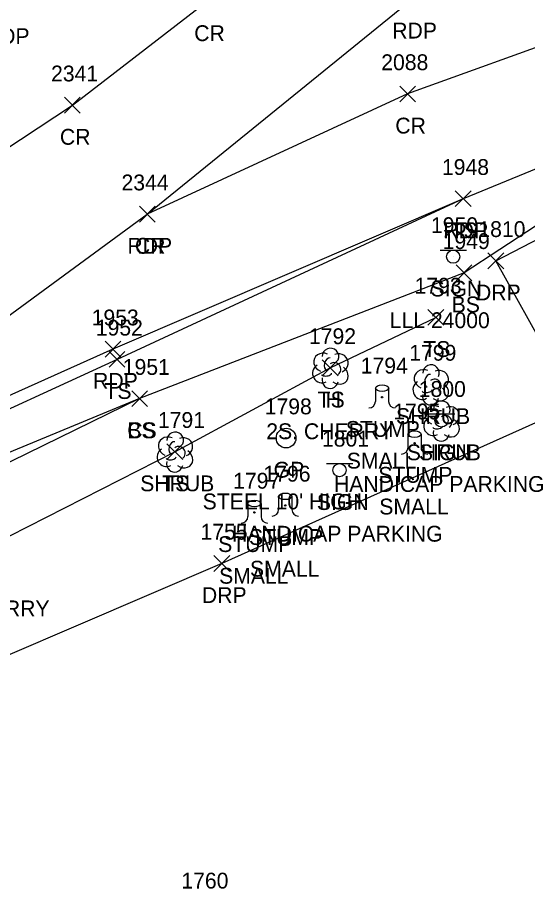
# Model space of a CAD drawing. Extents: x 1477930 to 1480780, y 774090 to 784647.
# Drawn here: x 1479170.3 to 1479234.8, y 774509.5 to 774618.7 of the extents above; entities that cross this region are included whole.
import ezdxf

# ---------------------------------------------------------------- set-up
doc = ezdxf.new("R2010")
doc.units = 0
for name, color, linetype in [('L_A', 7, 'Continuous'), ('L_C', 7, 'Continuous'), ('L_I', 7, 'Continuous'), ('L_TIC', 7, 'Continuous'), ('LELB', 7, 'Continuous'), ('LSH', 7, 'Continuous'), ('LTD', 7, 'Continuous'), ('LTS', 7, 'Continuous'), ('P_A', 7, 'Continuous'), ('P_I', 7, 'Continuous'), ('P_TIC', 7, 'Continuous'), ('PET', 7, 'Continuous'), ('PRC', 7, 'Continuous'), ('R_A', 7, 'Continuous'), ('R_C', 7, 'Continuous'), ('R_I', 7, 'Continuous'), ('R_TIC', 7, 'Continuous'), ('RDP', 7, 'Continuous'), ('RGP', 7, 'Continuous'), ('S_A', 7, 'Continuous'), ('S_C', 7, 'Continuous'), ('S_I', 7, 'Continuous'), ('SSGN', 7, 'Continuous')]:
    doc.layers.add(name, color=color, linetype=linetype)

msp = doc.modelspace()

# ---------------------------------------------------------------- linework, layer by layer
at = {"layer": 'L_TIC'}
for points in [[(1479225.65, 774594.78), (1479227.65, 774596.78)], [(1479227.65, 774594.78), (1479225.65, 774596.78)], [(1479225.75, 774585.42), (1479227.75, 774587.42)], [(1479227.75, 774585.42), (1479225.75, 774587.42)], [(1479222.19, 774579.79), (1479224.19, 774581.79)], [(1479224.19, 774579.79), (1479222.19, 774581.79)], [(1479181.92, 774574.49), (1479183.92, 774576.49)], [(1479183.92, 774574.49), (1479181.92, 774576.49)], [(1479208.85, 774573.41), (1479210.85, 774575.41)], [(1479210.85, 774573.41), (1479208.85, 774575.41)], [(1479184.77, 774569.53), (1479186.77, 774571.53)], [(1479186.77, 774569.53), (1479184.77, 774571.53)], [(1479184.77, 774569.53), (1479186.77, 774571.53)], [(1479186.77, 774569.53), (1479184.77, 774571.53)], [(1479189.21, 774562.83), (1479191.21, 774564.83)], [(1479191.21, 774562.83), (1479189.21, 774564.83)]]:
    msp.add_lwpolyline(points, dxfattribs=at)
at = {"layer": 'LELB'}
for points in [[(1479249.3, 774601.16), (1479226.75, 774586.42), (1479185.77, 774570.53), (1479139.55, 774551.45), (1479091.04, 774529.14), (1479044.11, 774505.82), (1478999.98, 774484.87), (1478971.08, 774463.97)], [(1479226.65, 774595.78), (1479182.92, 774575.49), (1479138.16, 774554.95), (1479088.98, 774532.71), (1479043.42, 774508.15), (1478998.98, 774486.89), (1478965.91, 774472.74)], [(1479036.25, 774486.8), (1479044.67, 774486.92), (1479065.86, 774499.81), (1479080.84, 774510.7), (1479101.55, 774520.78), (1479124.46, 774532.02), (1479145.39, 774541.96), (1479167.01, 774552.04), (1479190.21, 774563.83), (1479209.85, 774574.41), (1479223.19, 774580.79)], [(1479185.77, 774570.53), (1479141.09, 774548.69), (1479093, 774525.51), (1479038.22, 774497.26), (1479003.84, 774479.49), (1478971.08, 774463.97)]]:
    msp.add_lwpolyline(points, dxfattribs=at)
at = {"layer": 'LSH'}
for p, q in [((1479222.53, 774572.32), (1479222.53, 774572.32)), ((1479222.53, 774572.32), (1479222.53, 774572.32)), ((1479223.89, 774567.75), (1479223.89, 774567.75)), ((1479223.89, 774567.75), (1479223.89, 774567.75)), ((1479190.21, 774563.83), (1479190.21, 774563.83)), ((1479190.21, 774563.83), (1479190.21, 774563.83))]:
    msp.add_line(p, q, dxfattribs=at)
for centre in [(1479222.58, 774573.75), (1479223.94, 774569.18), (1479190.26, 774565.26)]:
    msp.add_arc(centre, 1.05, 335.5272, 180.9563, dxfattribs=at)
for centre, major_axis, ratio, start_param, end_param in [((1479221.74, 774572.98), (1.21, -0.51), 0.895232, 1.570796, 4.712389), ((1479223.57, 774572.9), (-1.14, -0.48), 0.949671, 1.570796, 4.712389), ((1479222.32, 774572.78), (-0.208, -0.792), 0.645439, 3.141593, 6.283185), ((1479223.03, 774572.15), (-0.5, 0.667), 0.989748, 3.141593, 6.283185), ((1479221.45, 774571.61), (0.58, -1.04), 0.959034, 3.141593, 6.283185), ((1479223.53, 774571.48), (-1.09, 0.79), 0.841452, 1.570796, 4.712389), ((1479222.53, 774570.82), (0.26, 1.06), 0.942809, 1.570796, 4.712389), ((1479222.08, 774571.57), (-0.625, -0.083), 0.423636, 0, 3.141593), ((1479223.1, 774568.41), (1.21, -0.51), 0.895232, 1.570796, 4.712389), ((1479223.68, 774568.21), (-0.208, -0.792), 0.645439, 3.141593, 6.283185), ((1479224.93, 774568.33), (-1.14, -0.48), 0.949671, 1.570796, 4.712389), ((1479222.81, 774567.04), (0.58, -1.04), 0.959034, 3.141593, 6.283185), ((1479224.39, 774567.58), (-0.5, 0.667), 0.989748, 3.141593, 6.283185), ((1479224.89, 774566.91), (-1.09, 0.79), 0.841452, 1.570796, 4.712389), ((1479223.89, 774566.25), (0.26, 1.06), 0.942809, 1.570796, 4.712389), ((1479223.43, 774567), (-0.625, -0.083), 0.423636, 0, 3.141593), ((1479189.42, 774564.49), (1.21, -0.51), 0.895232, 1.570796, 4.712389), ((1479191.25, 774564.41), (-1.14, -0.48), 0.949671, 1.570796, 4.712389), ((1479190, 774564.29), (-0.208, -0.792), 0.645439, 3.141593, 6.283185), ((1479190.71, 774563.66), (-0.5, 0.667), 0.989748, 3.141593, 6.283185), ((1479189.13, 774563.12), (0.58, -1.04), 0.959034, 3.141593, 6.283185), ((1479191.21, 774563), (-1.09, 0.79), 0.841452, 1.570796, 4.712389), ((1479190.21, 774562.33), (0.26, 1.06), 0.942809, 1.570796, 4.712389), ((1479189.75, 774563.08), (-0.625, -0.083), 0.423636, 0, 3.141593)]:
    msp.add_ellipse(centre, major_axis=major_axis, ratio=ratio, start_param=start_param, end_param=end_param, dxfattribs=at)
at = {"layer": 'LTD'}
msp.add_line((1479209.85, 774574.41), (1479209.85, 774574.41), dxfattribs=at)
msp.add_line((1479209.85, 774574.41), (1479209.85, 774574.41), dxfattribs=at)
msp.add_arc((1479209.89, 774575.85), 1.05, 335.5272, 180.9563, dxfattribs=at)
for centre, major_axis, ratio, start_param, end_param in [((1479209.06, 774575.08), (1.21, -0.51), 0.895232, 1.570796, 4.712389), ((1479210.89, 774575), (-1.14, -0.48), 0.949671, 1.570796, 4.712389), ((1479209.64, 774574.87), (-0.208, -0.792), 0.645439, 3.141593, 6.283185), ((1479208.77, 774573.7), (0.58, -1.04), 0.959034, 3.141593, 6.283185), ((1479210.35, 774574.25), (-0.5, 0.667), 0.989748, 3.141593, 6.283185), ((1479210.85, 774573.58), (-1.09, 0.79), 0.841452, 1.570796, 4.712389), ((1479209.85, 774572.91), (0.26, 1.06), 0.942809, 1.570796, 4.712389), ((1479209.39, 774573.66), (-0.625, -0.083), 0.423636, 0, 3.141593)]:
    msp.add_ellipse(centre, major_axis=major_axis, ratio=ratio, start_param=start_param, end_param=end_param, dxfattribs=at)
at = {"layer": 'LTS'}
for p, q in [((1479215.56, 774571.84), (1479215.56, 774570.18)), ((1479217.23, 774571.68), (1479217.23, 774571.84)), ((1479217.23, 774571.84), (1479217.23, 774570.18)), ((1479216.4, 774570.7), (1479216.4, 774570.7)), ((1479216.4, 774570.7), (1479216.4, 774570.7)), ((1479216.4, 774570.68), (1479216.4, 774570.68)), ((1479219.67, 774566.04), (1479219.67, 774564.37)), ((1479221.34, 774565.87), (1479221.34, 774566.04)), ((1479221.34, 774566.04), (1479221.34, 774564.37)), ((1479220.5, 774564.9), (1479220.5, 774564.9)), ((1479220.5, 774564.9), (1479220.5, 774564.9)), ((1479220.5, 774564.87), (1479220.5, 774564.87)), ((1479203.33, 774558.19), (1479203.33, 774556.53)), ((1479205, 774558.03), (1479205, 774558.19)), ((1479205, 774558.19), (1479205, 774556.53)), ((1479199.44, 774557.3), (1479199.44, 774555.64)), ((1479201.11, 774557.14), (1479201.11, 774557.3)), ((1479201.11, 774557.3), (1479201.11, 774555.64)), ((1479204.17, 774557.05), (1479204.17, 774557.05)), ((1479204.17, 774557.05), (1479204.17, 774557.05)), ((1479204.17, 774557.03), (1479204.17, 774557.03)), ((1479200.27, 774556.16), (1479200.27, 774556.16)), ((1479200.27, 774556.16), (1479200.27, 774556.16)), ((1479200.27, 774556.14), (1479200.27, 774556.14))]:
    msp.add_line(p, q, dxfattribs=at)
for centre in [(1479216.4, 774570.7), (1479220.5, 774564.9), (1479204.17, 774557.05), (1479200.27, 774556.16)]:
    msp.add_circle(centre, 0.0833, dxfattribs=at)
for centre, start, end in [((1479214.73, 774570.18), 270, 360), ((1479218.06, 774570.18), 180, 270), ((1479218.84, 774564.37), 270, 360), ((1479222.17, 774564.37), 180, 270), ((1479198.61, 774555.64), 270, 360), ((1479201.94, 774555.64), 180, 270), ((1479202.5, 774556.53), 270, 360), ((1479205.83, 774556.53), 180, 270)]:
    msp.add_arc(centre, 0.833, start, end, dxfattribs=at)
for centre in [(1479216.4, 774571.84), (1479220.5, 774566.04), (1479204.17, 774558.19), (1479200.27, 774557.3)]:
    msp.add_ellipse(centre, major_axis=(-0.833, 0), ratio=0.5, dxfattribs=at)
at = {"layer": 'P_TIC'}
for points in [[(1479218.63, 774608.01), (1479220.63, 774610.01)], [(1479220.63, 774608.01), (1479218.63, 774610.01)], [(1479176.27, 774606.59), (1479178.27, 774608.59)], [(1479178.27, 774606.59), (1479176.27, 774608.59)], [(1479225.65, 774594.78), (1479227.65, 774596.78)], [(1479227.65, 774594.78), (1479225.65, 774596.78)], [(1479185.74, 774592.83), (1479187.74, 774594.83)], [(1479187.74, 774592.83), (1479185.74, 774594.83)], [(1479185.74, 774592.83), (1479187.74, 774594.83)], [(1479187.74, 774592.83), (1479185.74, 774594.83)], [(1479181.4, 774575.78), (1479183.4, 774577.78)], [(1479183.4, 774575.78), (1479181.4, 774577.78)]]:
    msp.add_lwpolyline(points, dxfattribs=at)
at = {"layer": 'PET'}
for points in [[(1479290.45, 774211), (1479306.91, 774277.39), (1479311.78, 774295.77), (1479318.73, 774320.25), (1479320.95, 774328.78), (1479324.18, 774341.9), (1479331.38, 774365.72), (1479345.79, 774423.22), (1479362.09, 774490.12), (1479368.03, 774516.32), (1479374.9, 774550.83), (1479383.52, 774593.51), (1479391.98, 774640.39), (1479380.39, 774660.29), (1479367.57, 774658.29), (1479344.84, 774648.04), (1479309.03, 774631.85), (1479275.88, 774616.72), (1479247.66, 774604.4), (1479226.65, 774595.78), (1479182.4, 774576.78), (1479137.48, 774556.65)], [(1478683.07, 774347.91), (1478727.99, 774368.69), (1478775.23, 774390.17), (1478824.48, 774413.21), (1478871.78, 774434.98), (1478928.06, 774460.83), (1478969.71, 774480.29), (1479018.44, 774502.95), (1479067.21, 774527.02), (1479117.77, 774550.82), (1479128.42, 774557.99), (1479157.72, 774572.57), (1479186.74, 774593.83), (1479220.19, 774621.01), (1479234.45, 774632.83)]]:
    msp.add_lwpolyline(points, dxfattribs=at)
at = {"layer": 'PRC'}
for points in [[(1480015.89, 775005.87), (1479971.79, 774982.46), (1479929.14, 774959.03), (1479892.61, 774942.34), (1479860.44, 774925.31), (1479806.49, 774896.54), (1479658.45, 774815.54), (1479643.75, 774807.57), (1479597.62, 774782.97), (1479555.61, 774761.16), (1479513.42, 774740.32), (1479471, 774718.6), (1479432.73, 774701.1), (1479418.32, 774694.97), (1479344.83, 774660.92), (1479298.6, 774640.39), (1479262.12, 774624.4), (1479219.63, 774609.01), (1479186.74, 774593.83)], [(1478654.38, 774346.99), (1478674.83, 774356.65), (1478696.18, 774365.99), (1478731.38, 774382.14), (1478814.02, 774421.35), (1478859.83, 774442.03), (1478906.42, 774463.43), (1478938.4, 774478.56), (1479002.95, 774508.43), (1479077.31, 774545.61), (1479120.22, 774569.96), (1479177.27, 774607.59), (1479194.24, 774620.68)]]:
    msp.add_lwpolyline(points, dxfattribs=at)
at = {"layer": 'R_TIC'}
for points in [[(1479229.77, 774586.94), (1479231.77, 774588.94)], [(1479231.77, 774586.94), (1479229.77, 774588.94)], [(1479195.16, 774548.72), (1479197.16, 774550.72)], [(1479197.16, 774548.72), (1479195.16, 774550.72)]]:
    msp.add_lwpolyline(points, dxfattribs=at)
at = {"layer": 'RDP'}
for points in [[(1479295.55, 774599.42), (1479293.43, 774602.58), (1479262.53, 774582.94), (1479259.85, 774587.38), (1479237.72, 774575.46), (1479230.77, 774587.94), (1479250.82, 774598.31)], [(1479368.03, 774516.32), (1479361.45, 774512.48), (1479346.66, 774511.39), (1479327.95, 774516.32), (1479324.53, 774520.66), (1479324.13, 774525.6), (1479326.57, 774530.65), (1479318.13, 774536.67), (1479298.46, 774520.25), (1479259.37, 774517.83), (1479242.33, 774516.7), (1479243.5, 774532.48), (1479249.65, 774538.58), (1479246.27, 774545.9), (1479253.38, 774552.86), (1479239.84, 774569.3), (1479196.16, 774549.72), (1479150.61, 774530.18)]]:
    msp.add_lwpolyline(points, dxfattribs=at)
at = {"layer": 'RGP'}
msp.add_line((1479204.27, 774565.55), (1479204.27, 774565.55), dxfattribs=at)
for radius in [1.25, 0.0833]:
    msp.add_circle((1479204.27, 774565.55), radius, dxfattribs=at)
at = {"layer": 'SSGN'}
for p, q in [((1479223.72, 774589.28), (1479227.06, 774589.28)), ((1479225.37, 774588.45), (1479225.37, 774588.45)), ((1479222.26, 774568.6), (1479225.6, 774568.6)), ((1479223.91, 774567.77), (1479223.91, 774567.77)), ((1479209.38, 774562.32), (1479212.71, 774562.32)), ((1479211.03, 774561.49), (1479211.03, 774561.49))]:
    msp.add_line(p, q, dxfattribs=at)
for centre in [(1479225.37, 774588.45), (1479223.91, 774567.77), (1479211.03, 774561.49)]:
    msp.add_circle(centre, 0.833, dxfattribs=at)

# ---------------------------------------------------------------- texts
at = {"layer": 'L_A'}
for s, p in [('TS', (1479225.06, 774590.78)), ('BS', (1479225.19, 774581.42)), ('TS', (1479221.6, 774575.79)), ('TS', (1479181.33, 774570.49)), ('TS', (1479208.26, 774569.41)), ('H', (1479209.28, 774569.41)), ('SHRUB', (1479218.16, 774567.32)), ('STUMP', (1479211.82, 774565.7)), ('CS', (1479184.21, 774565.53)), ('BS', (1479184.21, 774565.53)), ('SHRUB', (1479219.52, 774562.75)), ('STUMP', (1479215.93, 774559.9)), ('SHRUB', (1479185.84, 774558.83)), ('TS', (1479188.62, 774558.83)), ('STUMP', (1479199.59, 774552.05)), ('STUMP', (1479195.69, 774551.16))]:
    msp.add_text(s, height=2, dxfattribs=at).set_placement(p)
at = {"layer": 'L_C'}
for s, p in [('2S. CHERRY', (1479201.77, 774565.41)), ('SMALL', (1479211.94, 774561.7)), ('SMALL', (1479216.04, 774555.9)), ('SMALL', (1479195.81, 774547.16)), ('SMALL', (1479199.71, 774548.05)), ('S. CHERRY', (1479159.83, 774543.04))]:
    msp.add_text(s, height=2, dxfattribs=at).set_placement(p)
at = {"layer": 'L_I'}
for s, p in [('1948', (1479223.96, 774598.78)), ('1949', (1479224.05, 774589.42)), ('1793', (1479220.5, 774583.79)), ('1952', (1479180.23, 774578.49)), ('1792', (1479207.16, 774577.41)), ('1792', (1479207.16, 774577.41)), ('1799', (1479219.83, 774575.32)), ('1951', (1479183.64, 774573.53)), ('1951', (1479183.64, 774573.53)), ('1794', (1479213.7, 774573.7)), ('1800', (1479221.03, 774570.75)), ('1795', (1479217.81, 774567.9)), ('1791', (1479188.08, 774566.83)), ('1791', (1479188.08, 774566.83)), ('1797', (1479197.58, 774559.16)), ('1796', (1479201.41, 774560.05)), ('1760', (1479191.04, 774508.66))]:
    msp.add_text(s, height=2, dxfattribs=at).set_placement(p)
at = {"layer": 'P_A'}
for s, p in [('RDP', (1479217.68, 774616.01)), ('RDP', (1479166.22, 774615.31)), ('CR', (1479192.67, 774615.68)), ('CR', (1479192.67, 774615.68)), ('CR', (1479218.07, 774604.01)), ('CR', (1479175.7, 774602.59)), ('RDP', (1479224.14, 774590.78)), ('RDP', (1479184.23, 774588.83)), ('CR', (1479185.17, 774588.83)), ('RDP', (1479179.89, 774571.78))]:
    msp.add_text(s, height=2, dxfattribs=at).set_placement(p)
at = {"layer": 'P_I'}
for s, p in [('2088', (1479216.29, 774612.01)), ('2341', (1479174.58, 774610.59)), ('1948', (1479223.96, 774598.78)), ('2344', (1479183.48, 774596.83)), ('2344', (1479183.48, 774596.83)), ('1953', (1479179.71, 774579.78))]:
    msp.add_text(s, height=2, dxfattribs=at).set_placement(p)
at = {"layer": 'R_A'}
for s, p in [('DRP', (1479228.26, 774582.94)), ('GP', (1479202.7, 774560.55)), ('DRP', (1479193.64, 774544.72))]:
    msp.add_text(s, height=2, dxfattribs=at).set_placement(p)
at = {"layer": 'R_C'}
msp.add_text("STEEL 10' HIGH", height=2, dxfattribs=at).set_placement((1479193.73, 774556.55))
at = {"layer": 'R_I'}
for s, p in [('1810', (1479228.56, 774590.94)), ('1798', (1479201.57, 774568.55)), ('1755', (1479193.46, 774552.72))]:
    msp.add_text(s, height=2, dxfattribs=at).set_placement(p)
at = {"layer": 'S_A'}
for p in [(1479222.51, 774583.43), (1479221.05, 774562.75), (1479208.16, 774556.47)]:
    msp.add_text('SIGN', height=2, dxfattribs=at).set_placement(p)
at = {"layer": 'S_C'}
for s, p in [('LLL 24000', (1479217.36, 774579.43)), ('HANDICAP PARKING', (1479210.32, 774558.75)), ('HANDICAP PARKING', (1479197.44, 774552.47))]:
    msp.add_text(s, height=2, dxfattribs=at).set_placement(p)
at = {"layer": 'S_I'}
for s, p in [('1950', (1479222.57, 774591.43)), ('1800', (1479221.03, 774570.75)), ('1801', (1479208.8, 774564.47))]:
    msp.add_text(s, height=2, dxfattribs=at).set_placement(p)

doc.saveas('drawing.dxf')
